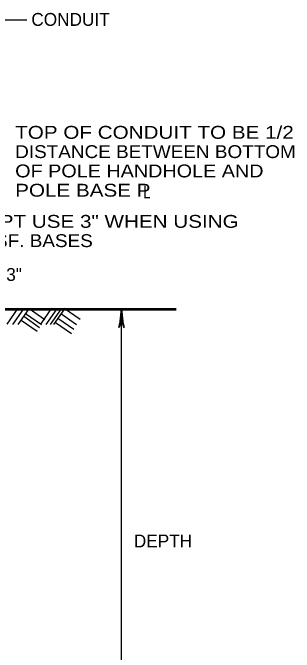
# Model space of a CAD drawing. Extents: x -560 to 120, y 26 to 466.
# Drawn here: x -111.1 to -67.3, y 113.4 to 212.8 of the extents above; entities that cross this region are included whole.
import ezdxf

# ---------------------------------------------------------------- set-up
doc = ezdxf.new("R2010")
doc.units = 0
doc.header["$LTSCALE"] = 0.8
doc.layers.add('1', color=7, linetype='Continuous', lineweight=53)

msp = doc.modelspace()

# ---------------------------------------------------------------- linework, layer by layer
at = {"layer": '1'}
for p, q in [((-150.3254, 166.6995), (-93.3471, 166.6995)), ((-101.8967, 166.6995), (-85.6935, 166.6995))]:
    msp.add_line(p, q, dxfattribs=at)
at = {"layer": '1', "lineweight": 25}
for p, q in [((-112.0178, 164.3798), (-110.2972, 166.8372)), ((-111.1176, 164.3047), (-109.3969, 166.7622)), ((-110.2924, 164.3047), (-108.5717, 166.7622)), ((-109.1197, 166.0291), (-106.6623, 164.3084)), ((-108.5946, 166.7792), (-106.1371, 165.0586)), ((-106.7664, 164.3798), (-105.0457, 166.8372)), ((-105.9412, 164.3047), (-104.2205, 166.7622)), ((-105.266, 164.3047), (-103.5453, 166.7622)), ((-104.7408, 164.3047), (-103.0202, 166.7622)), ((-103.6432, 166.0291), (-101.1857, 164.3084)), ((-103.1181, 166.8543), (-100.6606, 165.1337)), ((-94.2062, 93.4865), (-94.2062, 166.6995)), ((-109.4198, 165.5789), (-106.9623, 163.8582)), ((-104.0934, 165.2788), (-101.6359, 163.5582)), ((-109.7949, 164.9787), (-107.3374, 163.2581)), ((-104.4685, 164.6037), (-102.011, 162.883))]:
    msp.add_line(p, q, dxfattribs=at)
msp.add_lwpolyline([(-114.7771, 207.9452), (-112.6022, 211.695), (-108.9266, 211.695)], dxfattribs=at)
at = {"layer": '1', "lineweight": 40}
for centre, major_axis, ratio, start_param, end_param in [((-94.4179, 165.579), (-0.1757, -1.7565), 0.07063, 6.2823074, 8.5597026), ((-93.93, 165.6083), (-0.1562, 1.7857), 0.122415, 0.8963533, 3.1415927)]:
    msp.add_ellipse(centre, major_axis=major_axis, ratio=ratio, start_param=start_param, end_param=end_param, dxfattribs=at)

# ---------------------------------------------------------------- texts
at = {"layer": '1'}
for s, p in [('CONDUIT', (-108.2347, 210.7365)), ('3"', (-112.1361, 171.0847)), ('DEPTH', (-92.2912, 129.6518))]:
    msp.add_text(s, height=2, dxfattribs=at).set_placement(p)
for s, width, p in [('TOP OF CONDUIT TO BE 1/2', 1.2, (-110.748, 193.1792)), ('DISTANCE BETWEEN BOTTOM', 1.1, (-110.748, 190.1792)), ('OF POLE HANDHOLE AND', 1.15, (-110.748, 187.1792)), ('POLE BASE P', 1.2, (-110.748, 184.1792)), ('L', 0.75, (-90.802, 183.8966)), ('EXCEPT USE 3" WHEN USING', 1.2, (-121.8897, 179.3371)), ('TRANSF. BASES', 1.1, (-121.8897, 176.3371))]:
    msp.add_text(s, height=2, dxfattribs=dict(at, width=width)).set_placement(p)

doc.saveas('drawing.dxf')
